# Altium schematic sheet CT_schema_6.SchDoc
size 405 x 220 mm
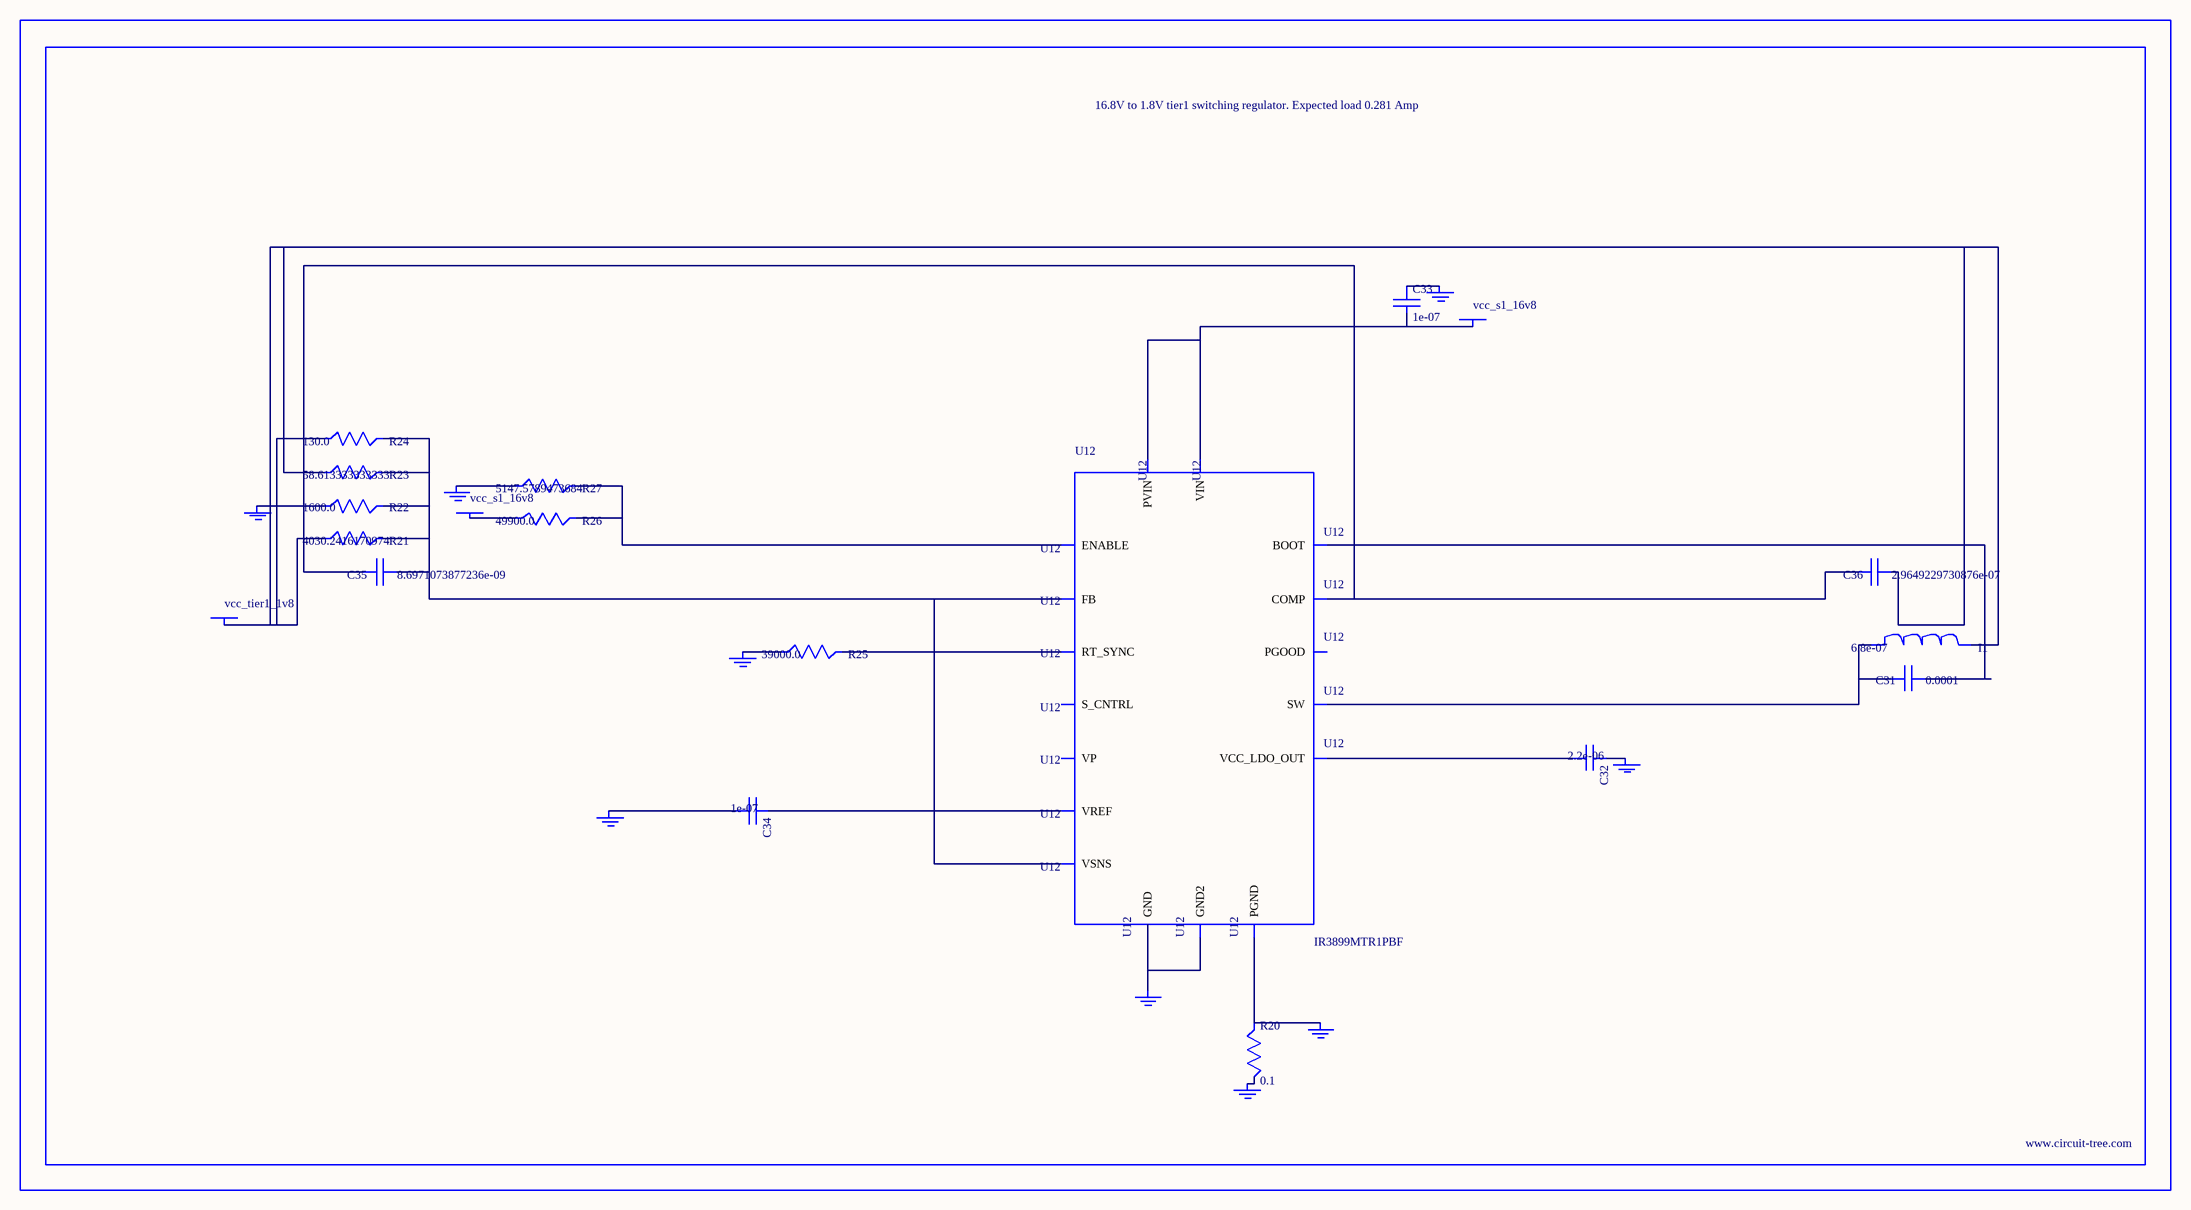
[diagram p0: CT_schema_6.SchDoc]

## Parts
BORDER5  (no value)
C31  0.0001  [C1210]
C32  2.2e-06  [C0603]
C33  1e-07  [C0402]
C34  1e-07  [C0402]
C35  8.6971073877236e-09  [R0603]
C36  2.9649229730876e-07  [R0603]
GND_INSTANCE_5_0  (no value)
GND_INSTANCE_5_1  (no value)
GND_INSTANCE_5_2  (no value)
GND_INSTANCE_5_3  (no value)
GND_INSTANCE_5_4  (no value)
GND_INSTANCE_5_5  (no value)
GND_INSTANCE_5_6  (no value)
GND_INSTANCE_5_7  (no value)
GND_INSTANCE_5_8  (no value)
I1  6.8e-07  [IND25X25CZ]
POWER_INSTANCE_5_0  vcc_s1_16v8
POWER_INSTANCE_5_1  vcc_s1_16v8
POWER_INSTANCE_5_2  vcc_tier1_1v8
R20  0.1  [R0603]
R21  4030.2416170974  [R0603]
R22  1600.0  [R0603]
R23  58.613333333333  [R0603]
R24  130.0  [R0603]
R25  39000.0  [R0603]
R26  49900.0  [R0603]
R27  5147.5789473684  [R0603]
U12  IR3899MTR1PBF  [IR3899MTR1PBF]

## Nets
NetC31_1: C31.1 U12.14(BOOT)
NetC31_2: C31.2 I1.1 U12.12(SW)
NetC32_1: C32.1 GND_INSTANCE_5_4.0(GND)
NetC32_2: C32.2 U12.10(VCC_LDO_OUT)
NetC33_1: C33.1 GND_INSTANCE_5_3.0(GND)
NetC33_2: C33.2 POWER_INSTANCE_5_0.0(PWR) U12.9(VIN) U12.13(PVIN)
NetC34_1: C34.1 U12.2(VREF)
NetC34_2: C34.2 GND_INSTANCE_5_1.0(GND)
NetC35_1: C35.1 R21.2 R22.2 R23.2 R24.2 U12.1(FB) U12.8(VSNS)
NetC35_2: C35.2 C36.2 U12.3(COMP)
NetC36_1: C36.1 I1.2 POWER_INSTANCE_5_2.0(PWR) R21.1 R23.1 R24.1
NetGND_INSTANCE_5_0_0: GND_INSTANCE_5_0.0(GND) R22.1
NetGND_INSTANCE_5_2_0: GND_INSTANCE_5_2.0(GND) R25.1
NetGND_INSTANCE_5_5_0: GND_INSTANCE_5_5.0(GND) R20.2
NetGND_INSTANCE_5_6_0: GND_INSTANCE_5_6.0(GND) R20.1 U12.11(PGND)
NetGND_INSTANCE_5_7_0: GND_INSTANCE_5_7.0(GND) R27.1
NetGND_INSTANCE_5_8_0: GND_INSTANCE_5_8.0(GND) U12.4(GND) U12.17(GND2)
NetPOWER_INSTANCE_5_1_0: POWER_INSTANCE_5_1.0(PWR) R26.1
NetR25_2: R25.2 U12.5(RT_SYNC)
NetR26_2: R26.2 R27.2 U12.15(ENABLE)

Not connected (* = marked no-connect by the designer): U12 6(S_CNTRL) 7(PGOOD) 16(VP)

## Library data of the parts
BORDER5 = BORDER_PAGE5
C31 = GRM32ER61A107ME20L
C32 = C0603C225K8RACTU
C33 C34 = C0402C104K3RACTU
C35 = C35
C36 = C36
GND_INSTANCE_5_0-GND_INSTANCE_5_8 = GND
I1 = IHLP2525CZERR68M01
POWER_INSTANCE_5_0-POWER_INSTANCE_5_2 = PWR
R20 = ERJ-3RSFR10V
R21 = R21
R22 = RC0603JR-071K6L
R23 = R23
R24 = RC0603JR-07130RL
R25 = RC0603JR-0739KL
R26 = RC0603FR-0749K9
R27 = R27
